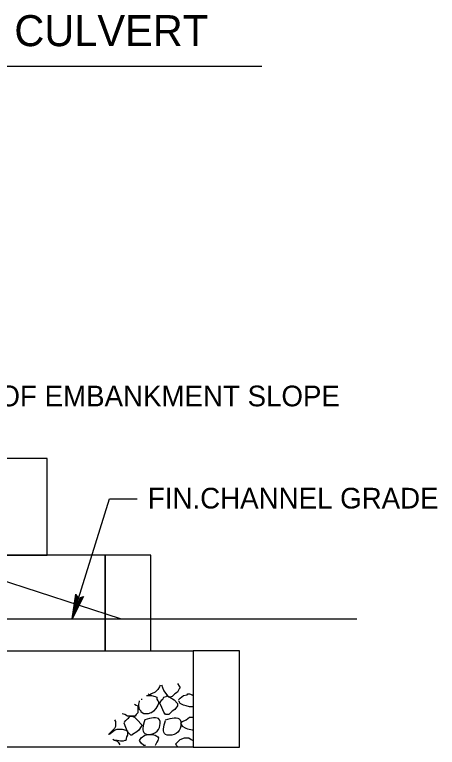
# Model space of a CAD drawing. Extents: x 593 to 1473, y 721 to 1315.
# Drawn here: x 1080.6 to 1141.9, y 992.3 to 1098.6 of the extents above; entities that cross this region are included whole.
import ezdxf

# ---------------------------------------------------------------- set-up
doc = ezdxf.new("R2010")
doc.units = 0
doc.layers.add('1', color=7, linetype='Continuous')
doc.layers.add('2', color=7, linetype='Continuous')

msp = doc.modelspace()

# ---------------------------------------------------------------- linework, layer by layer
at = {"layer": '1'}
msp.add_lwpolyline([(1090.36, 1014.09), (1090.09, 1014.04), (1088.94, 1010.96), (1090.36, 1014.09), (1090.56, 1014.21), (1088.94, 1010.96), (1089.76, 1014.14), (1089.56, 1014.32), (1088.94, 1010.96), (1089.46, 1014.55), (1089.56, 1014.32)], dxfattribs=at)
msp.add_lwpolyline([(1090.36, 1014.09), (1090.09, 1014.04), (1088.94, 1010.96), (1090.36, 1014.09), (1090.56, 1014.21), (1088.94, 1010.96), (1089.76, 1014.14), (1089.56, 1014.32), (1088.94, 1010.96), (1089.46, 1014.55), (1089.56, 1014.32)], dxfattribs=at)
at = {"layer": '2'}
for p, q in [((1059.42, 1091.14), (1116.42, 1091.14)), ((1095.94, 1010.96), (1022.95, 1034.71)), ((1088.94, 1010.96), (1094.34, 1028.36)), ((1094.34, 1028.36), (1098.35, 1028.36)), ((1022.95, 1010.96), (1130.19, 1010.96))]:
    msp.add_line(p, q, dxfattribs=at)
for points in [[(1078.69, 1034.21), (1078.69, 1020.21), (1085.32, 1020.21), (1085.32, 1034.21)], [(1078.69, 1020.21), (1078.69, 1006.34), (1093.69, 1006.34), (1093.69, 1020.21)], [(1093.69, 1020.21), (1093.69, 1006.34), (1100.32, 1006.34), (1100.32, 1020.21)], [(1106.44, 1006.34), (1106.44, 992.34), (1078.69, 992.34), (1078.69, 1006.34)], [(1106.44, 1006.34), (1106.44, 992.34), (1113.19, 992.34), (1113.19, 1006.34)]]:
    msp.add_lwpolyline(points, close=True, dxfattribs=at)
for points in [[(1101.57, 1001.09), (1101.32, 1000.71)], [(1101.69, 1001.34), (1101.57, 1001.09)], [(1101.69, 1001.34), (1101.69, 1001.34)], [(1102.19, 1000.59), (1101.94, 1001.34)], [(1102.07, 1001.34), (1102.07, 1001.34)], [(1104.19, 1001.59), (1104.44, 1001.21)], [(1104.44, 1001.21), (1104.57, 1000.96)], [(1104.57, 1000.96), (1104.44, 1000.84)], [(1100.07, 999.96), (1099.94, 1000.09)], [(1099.94, 1000.09), (1099.94, 1000.09)], [(1100.19, 999.96), (1100.07, 999.96)], [(1100.44, 1000.09), (1100.19, 999.96)], [(1100.94, 1000.34), (1100.44, 1000.09)], [(1101.32, 1000.71), (1100.94, 1000.34)], [(1102.69, 999.96), (1102.19, 1000.59)], [(1102.82, 999.71), (1102.69, 999.96)], [(1103.82, 1000.09), (1103.44, 999.71)], [(1104.19, 1000.34), (1103.82, 1000.09)], [(1104.44, 1000.84), (1104.19, 1000.34)], [(1105.07, 999.84), (1105.57, 999.96)], [(1105.57, 999.96), (1105.69, 1000.09)], [(1105.69, 1000.09), (1105.94, 1000.09)], [(1105.94, 1000.09), (1106.32, 999.96)], [(1106.32, 999.96), (1106.44, 999.84)], [(1098.57, 998.59), (1098.69, 998.96)], [(1098.69, 998.96), (1098.69, 999.09)], [(1098.69, 999.09), (1098.69, 999.09)], [(1098.94, 999.34), (1099.07, 999.34)], [(1099.69, 999.84), (1099.94, 999.84)], [(1099.94, 999.84), (1100.44, 999.84)], [(1100.44, 999.84), (1100.94, 999.71)], [(1100.94, 999.71), (1101.19, 999.59)], [(1101.19, 999.59), (1101.19, 999.34)], [(1101.19, 999.34), (1101.32, 999.09)], [(1101.32, 999.09), (1101.44, 998.96)], [(1101.44, 998.96), (1101.44, 998.71)], [(1101.94, 998.09), (1101.57, 998.84)], [(1101.69, 998.84), (1101.94, 999.21)], [(1101.94, 999.21), (1102.07, 999.34)], [(1102.07, 999.34), (1102.19, 999.59)], [(1102.19, 999.59), (1102.57, 999.71)], [(1102.57, 999.71), (1102.69, 999.84)], [(1102.69, 999.84), (1102.69, 999.84)], [(1102.69, 999.84), (1103.07, 999.59)], [(1102.94, 999.59), (1102.82, 999.71)], [(1103.07, 999.59), (1102.94, 999.59)], [(1103.44, 999.71), (1103.07, 999.59)], [(1103.07, 999.59), (1103.69, 999.21)], [(1103.69, 999.21), (1104.19, 998.71)], [(1104.32, 999.21), (1104.57, 999.46)], [(1104.44, 998.96), (1104.32, 999.09)], [(1104.57, 998.71), (1104.44, 998.96)], [(1104.57, 999.46), (1105.07, 999.84)], [(1097.94, 998.59), (1098.19, 998.46)], [(1098.19, 998.46), (1098.44, 998.34)], [(1098.44, 998.34), (1098.44, 998.21)], [(1098.44, 998.21), (1098.44, 997.96)], [(1098.44, 997.96), (1098.44, 997.59)], [(1098.57, 998.34), (1098.57, 998.59)], [(1098.69, 997.84), (1098.57, 998.34)], [(1098.94, 997.59), (1098.69, 997.84)], [(1101.07, 997.96), (1100.69, 997.59)], [(1101.19, 998.21), (1101.07, 997.96)], [(1101.32, 998.46), (1101.19, 998.21)], [(1101.44, 998.71), (1101.32, 998.46)], [(1102.19, 997.46), (1101.94, 998.09)], [(1103.82, 997.84), (1103.44, 997.59)], [(1104.19, 998.34), (1103.82, 997.84)], [(1104.19, 998.71), (1104.19, 998.46)], [(1104.19, 998.46), (1104.19, 998.34)], [(1105.07, 998.46), (1104.57, 998.71)], [(1105.44, 998.34), (1105.07, 998.46)], [(1105.94, 998.21), (1105.44, 998.34)], [(1106.44, 998.21), (1105.94, 998.21)], [(1106.44, 998.34), (1106.44, 998.21)], [(1096.57, 997.09), (1096.19, 997.21)], [(1096.94, 996.84), (1096.57, 997.09)], [(1097.44, 996.84), (1096.94, 996.84)], [(1097.07, 996.59), (1097.32, 996.84)], [(1097.32, 996.84), (1097.44, 996.84)], [(1097.44, 996.84), (1097.57, 996.84)], [(1097.94, 996.84), (1097.44, 996.84)], [(1097.57, 996.84), (1097.94, 996.71)], [(1098.07, 996.84), (1097.94, 996.84)], [(1097.94, 996.71), (1098.44, 996.21)], [(1098.19, 997.09), (1098.07, 996.84)], [(1098.44, 997.34), (1098.19, 997.09)], [(1098.44, 997.59), (1098.44, 997.34)], [(1098.94, 997.46), (1098.94, 997.59)], [(1099.32, 997.21), (1098.94, 997.46)], [(1099.69, 997.21), (1099.32, 997.21)], [(1099.94, 997.21), (1099.69, 997.21)], [(1100.32, 997.34), (1099.94, 997.21)], [(1100.44, 997.34), (1100.32, 997.34)], [(1100.69, 997.59), (1100.44, 997.34)], [(1102.44, 997.09), (1102.19, 997.46)], [(1102.69, 997.09), (1102.44, 997.09)], [(1102.94, 997.09), (1102.69, 997.09)], [(1102.69, 997.09), (1102.69, 997.09)], [(1103.44, 997.59), (1102.94, 997.09)], [(1105.44, 996.34), (1105.94, 996.71)], [(1105.94, 996.71), (1106.07, 996.71)], [(1106.07, 996.71), (1106.44, 996.71)], [(1106.44, 996.71), (1106.44, 996.71)], [(1095.07, 996.34), (1095.19, 996.09)], [(1095.19, 996.09), (1095.19, 995.71)], [(1095.19, 995.71), (1095.19, 995.59)], [(1096.44, 995.96), (1096.69, 996.21)], [(1096.69, 995.21), (1096.44, 995.84)], [(1096.69, 996.21), (1096.94, 996.46)], [(1096.94, 996.46), (1097.07, 996.59)], [(1098.44, 996.21), (1098.94, 995.71)], [(1098.94, 995.71), (1099.07, 995.59)], [(1104.69, 995.84), (1104.94, 996.09)], [(1104.82, 995.59), (1104.69, 995.84)], [(1104.94, 996.09), (1105.44, 996.34)], [(1094.57, 994.59), (1094.19, 994.21)], [(1094.82, 994.84), (1094.57, 994.59)], [(1094.57, 994.46), (1095.07, 994.84)], [(1095.07, 995.09), (1094.82, 994.84)], [(1095.19, 995.34), (1095.07, 995.09)], [(1095.07, 994.84), (1095.44, 994.96)], [(1095.19, 995.59), (1095.19, 995.34)], [(1095.44, 994.96), (1095.69, 994.96)], [(1095.69, 994.96), (1095.94, 994.96)], [(1095.94, 994.96), (1096.19, 994.96)], [(1096.19, 994.96), (1096.69, 994.84)], [(1096.94, 994.59), (1096.69, 995.21)], [(1096.69, 994.84), (1096.94, 994.71)], [(1096.94, 994.71), (1096.94, 994.59)], [(1097.32, 994.21), (1096.94, 994.59)], [(1096.94, 994.59), (1096.94, 994.46)], [(1098.32, 994.59), (1097.69, 994.21)], [(1098.57, 994.84), (1098.32, 994.59)], [(1098.94, 995.34), (1098.57, 994.84)], [(1099.07, 995.59), (1098.94, 995.34)], [(1104.94, 995.34), (1104.82, 995.59)], [(1105.44, 995.09), (1104.94, 995.34)], [(1105.69, 994.96), (1105.44, 995.09)], [(1106.32, 994.84), (1105.69, 994.96)], [(1106.44, 994.84), (1106.32, 994.84)], [(1094.19, 994.21), (1094.19, 994.21)], [(1094.32, 994.21), (1094.57, 994.46)], [(1096.82, 993.84), (1096.69, 993.34)], [(1096.94, 994.09), (1096.82, 993.84)], [(1096.94, 994.46), (1096.94, 994.09)], [(1097.44, 994.09), (1097.32, 994.21)], [(1097.57, 994.09), (1097.44, 994.09)], [(1097.69, 994.21), (1097.57, 994.09)], [(1098.69, 993.34), (1098.94, 993.71)], [(1098.94, 993.71), (1099.44, 994.09)], [(1099.44, 994.09), (1099.94, 994.21)], [(1099.94, 994.21), (1099.94, 994.21)], [(1099.94, 994.21), (1100.44, 994.21)], [(1100.44, 994.21), (1100.57, 994.21)], [(1100.57, 994.21), (1100.94, 994.09)], [(1100.94, 994.09), (1101.19, 993.96)], [(1101.19, 993.96), (1101.32, 993.84)], [(1101.32, 993.84), (1101.44, 993.71)], [(1101.44, 993.71), (1101.32, 993.34)], [(1104.57, 993.46), (1105.19, 993.71)], [(1105.19, 993.71), (1105.19, 993.71)], [(1105.19, 993.71), (1105.69, 993.71)], [(1105.69, 993.71), (1105.82, 993.71)], [(1105.82, 993.71), (1106.19, 993.46)], [(1095.07, 993.34), (1094.82, 993.46)], [(1095.44, 993.34), (1095.07, 993.34)], [(1095.19, 993.34), (1095.44, 993.21)], [(1095.94, 993.21), (1095.44, 993.34)], [(1095.44, 993.21), (1095.57, 993.09)], [(1095.57, 993.09), (1095.69, 992.96)], [(1095.69, 992.96), (1095.82, 992.71)], [(1096.32, 993.21), (1095.94, 993.21)], [(1096.57, 993.34), (1096.32, 993.21)], [(1096.69, 993.34), (1096.57, 993.34)], [(1098.82, 993.09), (1098.69, 993.34)], [(1098.94, 992.96), (1098.82, 993.09)], [(1099.32, 992.59), (1098.94, 992.96)], [(1099.57, 992.59), (1099.32, 992.59)], [(1101.19, 993.09), (1100.94, 992.59)], [(1100.94, 992.59), (1100.94, 992.59)], [(1101.32, 993.34), (1101.19, 993.09)], [(1103.94, 992.84), (1104.19, 993.09)], [(1104.07, 992.59), (1103.94, 992.84)], [(1104.19, 992.46), (1104.07, 992.59)], [(1104.19, 993.09), (1104.57, 993.46)], [(1106.19, 993.46), (1106.44, 993.34)], [(1106.44, 993.34), (1106.44, 993.34)], [(1106.44, 992.59), (1106.44, 992.46)], [(1106.44, 992.46), (1106.44, 992.34)]]:
    msp.add_lwpolyline(points, dxfattribs=at)
for points in [[(1099.44, 996.34), (1101.57, 996.34), (1101.57, 995.21), (1100.69, 994.34), (1099.44, 994.34), (1099.44, 996.34)], [(1102.44, 996.34), (1104.57, 996.34), (1104.57, 995.09), (1103.69, 994.21), (1102.44, 994.21), (1102.44, 996.21)]]:
    msp.add_spline(points, degree=3, dxfattribs=at)

# ---------------------------------------------------------------- texts
for s, height, p in [('THRU CULVERT', 4.5, (1062.16, 1094.02)), ('TOE OF EMBANKMENT SLOPE', 3, (1068.88, 1041.79)), ('FIN.CHANNEL GRADE', 3, (1099.9, 1026.97))]:
    msp.add_text(s, height=height, dxfattribs=at).set_placement(p)

doc.saveas('drawing.dxf')
